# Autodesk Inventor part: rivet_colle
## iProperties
Created: 2011-01
Part Number: rivet_colle
Document SubType Name: Modeling
Designer: eric
Density: 1 g/cm^3
Mass: 0.094507 g
Surface Area: 1.805 cm^2
Volume: 0.094507 cm^3
Author: eric
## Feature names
1. Base1
